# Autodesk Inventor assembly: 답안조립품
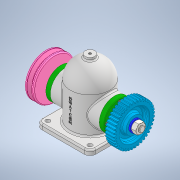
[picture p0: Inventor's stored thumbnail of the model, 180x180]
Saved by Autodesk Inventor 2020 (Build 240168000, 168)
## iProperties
Created: 2021-07
Part Number: 답안조립품
Document SubType Name: Assembly
Designer: Owner
Author: Owner
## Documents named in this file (14)
- C:\Users\Owner\Desktop\710716V1010\답안조립품.iam
- C:\Users\Owner\Desktop\710716V1010\본체.ipt
- C:\Users\Owner\Desktop\710716V1010\V-벨트풀리.ipt
- V-벨트풀리.ipt
- C:\Users\Owner\Desktop\710716V1010\너트 M12x1.25.ipt
- C:\Users\Owner\Desktop\710716V1010\베어링 6203.ipt
- C:\Users\Owner\Desktop\710716V1010\볼트 M4.ipt
- C:\Users\Owner\Desktop\710716V1010\부시.ipt
- C:\Users\Owner\Desktop\710716V1010\스퍼기어.ipt
- C:\Users\Owner\Desktop\710716V1010\오일 실 26 38 8.ipt
- C:\Users\Owner\Desktop\710716V1010\와셔 12x24.ipt
- C:\Users\Owner\Desktop\710716V1010\축.ipt
- C:\Users\Owner\Desktop\710716V1010\커버.ipt
- C:\Users\Owner\Desktop\710716V1010\키 5x5x12.ipt
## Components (1 placed, 1 different names)
1. V-벨트풀리:1 — 플러쉬:2
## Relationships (1: Flush 1)
- 플러쉬:2 [Flush]: V-벨트풀리:1
